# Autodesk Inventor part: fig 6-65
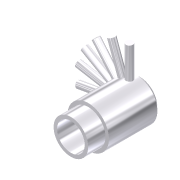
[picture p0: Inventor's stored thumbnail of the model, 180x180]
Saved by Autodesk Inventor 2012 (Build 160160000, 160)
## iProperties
Shininess: 77.0
Angle Display Precision: 2
Document Length Units: 11269
Document Angle Units: 11279
Document Time Units: 11290
Document Mass Units: 11283
Document Length Units Precision: 3
Document Angle Units Precision: 2
Compacted: True
Created: 2001-12
Part Number: fig 6-65
Document SubType Name: Modeling
Designer: Renu Muthoo
Density: 1 g/cm^3
Material: Default
Density: 0.0
Volumn: 0.0
Area: 0.0
PropertySet Name: Model Information
Control State: 0
Master: False
Checked Out: False
Author: Renu Muthoo
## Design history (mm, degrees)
sketch "Sketch2"
  geometry: L1 (-9.573, -4.327)-(-9.573, -5.327); L2 (-9.573, -5.327)-(-4.573, -5.327); L3 (-4.573, -5.327)-(-4.573, -6.327); L4 (-4.573, -6.327)-(9.427, -6.327); L5 (9.427, -6.327)-(10.427, -5.327); L6 (10.427, -5.327)-(10.427, -4.327); L7 (10.427, -4.327)-(-9.573, -4.327); L8 (-13.687, -0.327)-(14, -0.327)
  constraints: 16 end point, 5 parallel, 1 perpendicular, 1 vertical
  dimensions: "d9" = 20 distance of L6.end L1.start; "d10" = 5 distance of L1.end L2.end; "d11" = 12 diameter of L4 L8; "d12" = 10 diameter of L2 L8; "d13" = 8 diameter of L7 L8; "d14" = 45 deg angle of L5 L4; "d15" = 1 horizontal distance of L5.end L4.end
revolve "Revolution2" sketch "Sketch2" stored, may be unused: angle "d16" = 90 deg
workplane "Work Plane1"
workplane "Work Plane2"
sketch "Sketch3"
  geometry: L1 (-4, 8)-(4, 8) reference; C1 r 1 at (-0.098, 5)
  constraints: 1 centre point
  dimensions: "d18" = 3 distance from line of L1 C1.centre; "d19" = 2 diameter of C1
extrude "Extrusion1" join sketch "Sketch3" distance "d20" = 10; taper "d21" = 0 deg
pattern_circular "Circular Pattern3" dims angle "d29" = 20 deg
body "Solid1"
other parameters: "d17" = -1
